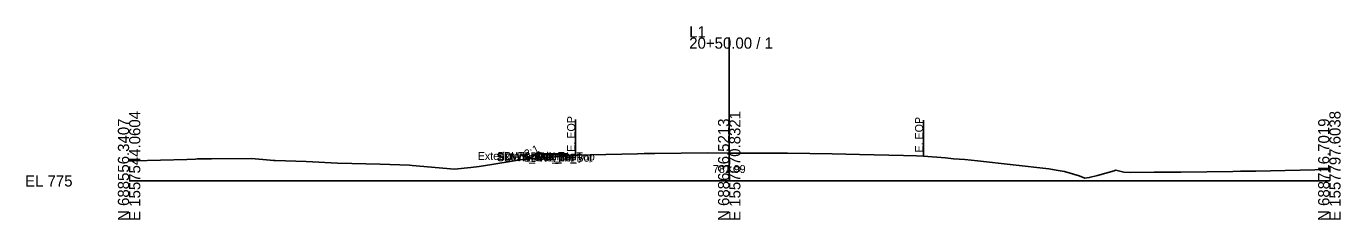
# Model space of a CAD drawing. Extents: x -26 to 2603, y -3010 to 9589.
# Drawn here: x -25.7 to 302.8, y 3990.3 to 4038.7 of the extents above; entities that cross this region are included whole.
import ezdxf

# ---------------------------------------------------------------- set-up
doc = ezdxf.new("R2010")
doc.units = 0
for name, color, linetype in [('Default', 7, 'Continuous'), ('Exist Cross Section Cell', 7, 'Continuous'), ('Exist XS Center Line Elevation Label', 7, 'Continuous'), ('Exist XS Ground Line', 7, 'Continuous'), ('Prop CMT Conc Surface', 7, 'Continuous'), ('Prop CMT Concrete Structures', 7, 'Continuous'), ('Prop CMT Slope Grass', 7, 'Continuous'), ('Prop XS Earthwork Shape', 7, 'Continuous'), ('Prop XS Label Text', 7, 'Continuous'), ('Prop XS Side Slope Text', 7, 'Continuous')]:
    doc.layers.add(name, color=color, linetype=linetype)

msp = doc.modelspace()

# ---------------------------------------------------------------- linework, layer by layer
at = {"layer": 'Exist Cross Section Cell'}
for p, q in [((150, 4000), (150, 4035.86)), ((0, 4000), (150, 4000)), ((150, 4000), (300, 4000))]:
    msp.add_line(p, q, dxfattribs=at)
at = {"layer": 'Exist XS Ground Line'}
msp.add_lwpolyline([(0, 4005.06), (1.31, 4005.06), (14.46, 4005.36), (16.59, 4005.48), (17.09, 4005.5), (17.41, 4005.5), (20.62, 4005.55), (30.6, 4005.62), (35.25, 4005.21), (36.07, 4005.15), (36.53, 4005.12), (44.24, 4004.9), (52.12, 4004.46), (62.78, 4004.19), (70.05, 4003.93), (70.77, 4003.86), (81.34, 4002.95), (85.4, 4003.35), (87.48, 4003.62), (90.65, 4004.12), (96.24, 4005.01), (99.48, 4005.51), (111.97, 4006.43), (115.21, 4006.54), (127.09, 4006.79), (128.74, 4006.83), (130.47, 4006.86), (131.37, 4006.87), (144.55, 4007.03), (150, 4006.97), (152.09, 4006.95), (164.55, 4006.93), (175.72, 4006.74), (182.57, 4006.6), (193.54, 4006.36), (196.78, 4006.29), (198.55, 4006.16), (204.09, 4005.75), (206.05, 4005.54), (208.91, 4005.33), (212.02, 4005.03), (229.85, 4003.03), (232.26, 4002.64), (233.78, 4002.39), (237.43, 4001.24), (238.91, 4000.73), (240, 4000.83), (242.09, 4001.38), (246.25, 4002.53), (246.55, 4002.66), (246.96, 4002.59), (248.61, 4002.23), (250.29, 4002.15), (256.25, 4002.16), (262.89, 4002.2), (275.84, 4002.36), (277.79, 4002.42), (278.83, 4002.44), (281.65, 4002.48), (300, 4002.89)], dxfattribs=at)
at = {"layer": 'Prop CMT Conc Surface'}
msp.add_lwpolyline([(108, 4006.8), (103, 4006.9)], dxfattribs=at)
at = {"layer": 'Prop CMT Concrete Structures'}
for points in [[(103, 4006.57), (103, 4006.9)], [(103, 4006.9), (108, 4006.8)], [(108, 4006.47), (103, 4006.57)], [(108, 4006.8), (108, 4006.47)], [(109.1, 4006.78), (109.1, 4005.77), (111.6, 4005.82)], [(109.6, 4006.28), (109.6, 4006.78), (109.1, 4006.78)], [(111.6, 4006.4), (109.6, 4006.28)], [(111.6, 4005.82), (111.6, 4006.4)]]:
    msp.add_lwpolyline(points, dxfattribs=at)
at = {"layer": 'Prop CMT Slope Grass'}
for p, q in [((102.5, 4006.91), (99.73, 4005.53)), ((103, 4006.9), (102.5, 4006.91)), ((109.1, 4006.78), (108, 4006.8))]:
    msp.add_line(p, q, dxfattribs=at)
at = {"layer": 'Prop XS Earthwork Shape'}
for points in [[(109.1, 4006.78), (108, 4006.8), (108, 4006.47), (103, 4006.57), (103, 4006.9), (102.5, 4006.91), (99.73, 4005.53), (109.1, 4006.22)], [(111.6, 4005.82), (111.6, 4006.4), (109.1, 4006.22), (109.1, 4005.77)]]:
    msp.add_lwpolyline(points, close=True, dxfattribs=at)
at = {"layer": 'Prop XS Label Text'}
for p, q in [((111.59, 4015.37), (111.59, 4006.37)), ((198.55, 4015.16), (198.55, 4006.16))]:
    msp.add_line(p, q, dxfattribs=at)

# ---------------------------------------------------------------- texts
at = {"layer": 'Default'}
for s, height, p in [('Exterior Boundary', 2, (87.14, 4005.24)), ('SDWK_Out_Top', 2, (91.93, 4005.24)), ('SDWK_Out_Bot', 2, (91.96, 4004.9)), ('Exterior Boundary', 2, (92.14, 4005.14)), ('SDWK_In_Top', 2, (98.55, 4005.14)), ('SDWK_In_Bot', 2, (98.58, 4004.8)), ('-', 0.0001, (0, 4000))]:
    msp.add_text(s, height=height, dxfattribs=at).set_placement(p)
at = {"layer": 'Exist Cross Section Cell'}
for s, p in [('L1', (140, 4035.86)), ('20+50.00 / 1', (140, 4033.06)), ('EL 775', (-26, 3998.6))]:
    msp.add_text(s, height=2.8, dxfattribs=at).set_placement(p)
for s, p in [('N 688556.3407', (0, 3990)), ('E 1557544.0604', (2.8, 3990)), ('N 688636.5213', (150, 3990)), ('E 1557670.8321', (152.8, 3990)), ('N 688716.7019', (300, 3990)), ('E 1557797.6038', (302.8, 3990))]:
    msp.add_text(s, height=2.8, rotation=90, dxfattribs=at).set_placement(p)
at = {"layer": 'Exist XS Center Line Elevation Label'}
msp.add_text('781.99', height=2, dxfattribs=at).set_placement((145.92, 4001.99))
at = {"layer": 'Prop XS Label Text'}
for p in [(111.49, 4007.3), (198.45, 4007.09)]:
    msp.add_text('E. EOP', height=2, rotation=90, dxfattribs=at).set_placement(p)
at = {"layer": 'Prop XS Side Slope Text'}
msp.add_text('2:1', height=2, rotation=26.5651, dxfattribs=at).set_placement((99.39, 4005.69))

doc.saveas('drawing.dxf')
